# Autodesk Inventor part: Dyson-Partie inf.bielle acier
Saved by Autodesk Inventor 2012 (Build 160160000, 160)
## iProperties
Created: 2012-11
Part Number: Dyson-Partie inf.bielle acier
Material: Default
Document SubType Name: Modeling
Designer: Administrateur
Density: 1 g/cm^3
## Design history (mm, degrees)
node "Dyson-Partie inf.bielle acier1"
node "Dyson-Partie inf.bielle acier"
node "Base1"
